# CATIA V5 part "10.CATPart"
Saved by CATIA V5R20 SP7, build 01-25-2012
Part number: skl_general
Publications: "Point A", "Point G", "Point D", "PoinT B", "Point C", "Point E", "Point F", "Plan yz"
Bounding box of the stored display mesh (mm): x 0 to 0, y -127.331 to 124.167, z 0 to 95.272
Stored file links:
  U:\IAO-Thinkmotion\TRAVAIL A RENDRE\10.CATPart
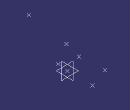
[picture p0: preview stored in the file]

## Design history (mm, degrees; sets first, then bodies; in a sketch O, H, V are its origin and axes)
Parameters
  AB = 30 mm
  BC = 75.6 mm {= 2.52*AB}
  DC = 43.2 mm {= 1.44*AB}
  BE = 133.2 mm {= 4.44*AB}
  CE = 126.9 mm {= 4.23*AB}
  EF = 253.5 mm {= 8.45*AB}
  GF = 75.6 mm {= 2.52*AB}
  AD = 70.5 mm {= 2.35*AB}
  AG = 83.1 mm {= 2.77*AB}
  DG = 74.4 mm {= 2.48*AB}
Set1
  Point1 "Point A": (0, 0, 0)
  Circle1 "Cercle AD": type CtrRad, Start 0, End 180, Center Point1, Support yz-plane, Radius 70.5 {= AD}, FirstDirection (0, 1, 0)
  Point2 "Point G": (0, 83.1 {= AG}, 0)
  Circle2 "CercleAG": type CtrRad, Start 0, End 180, Center Point2, Support yz-plane, Radius 74.4 {= DG}, FirstDirection (0, 1, 0)
  Intersect1: ToIntersect1 Circle2, ToIntersect2 Circle1
  Extract1 "Point D": ExtractElem vertex of Intersect1
  Circle3 "Cercle AB": type CtrRad, Start 0, End 180, Center Point1, Support yz-plane, Radius 30 {= AB}, FirstDirection (0, 1, 0)
  Point3 "PoinT B": type OnCurve, Support Circle3, RefPoint {extremum Reference Circle3, Direction (1, 2, 3)}, Length 60 {= 2*AB}
  Circle4 "Cercle GF": type CtrRad, Start 0, End 180, Center Point2, Support yz-plane, Radius 75.6 {= GF}, FirstDirection (0, 1, 0)
  Circle5 "Cercle BC": type CtrRad, Start 0, End 180, Center Point3, Support yz-plane, Radius 75.6 {= BC}, FirstDirection (0, 1, 0)
  Circle6: type CtrRad, Start 0, End 180, Center Extract1, Support yz-plane, Radius 43.2 {= DC}, FirstDirection (0, 1, 0)
  Intersect2: ToIntersect1 Circle6, ToIntersect2 Circle5
  Extract2 "Point C": ExtractElem vertex of Intersect2
  Circle7: type CtrRad, Start 0, End 180, Center Point3, Support yz-plane, Radius 133.2 {= BE}, FirstDirection (0, 1, 0)
  Circle8: type CtrRad, Start 0, End 180, Center Extract2, Support yz-plane, Radius 126.9 {= CE}, FirstDirection (0, 1, 0)
  Intersect3: ToIntersect1 Circle8, ToIntersect2 Circle7
  Extract3 "Point E": ExtractElem vertex of Intersect3
  Circle9: type CtrRad, Start 0, End 180, Center Extract3, Support yz-plane, Radius 253.5 {= EF}, FirstDirection (0, 1, 0)
  Intersect4: ToIntersect1 Circle4, ToIntersect2 Circle9
  Extract4 "Point F": ExtractElem vertex of Intersect4
Body1 (main body)
Relations
  GF = AB (deactivated)
  AG = 2.77* (deactivated)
